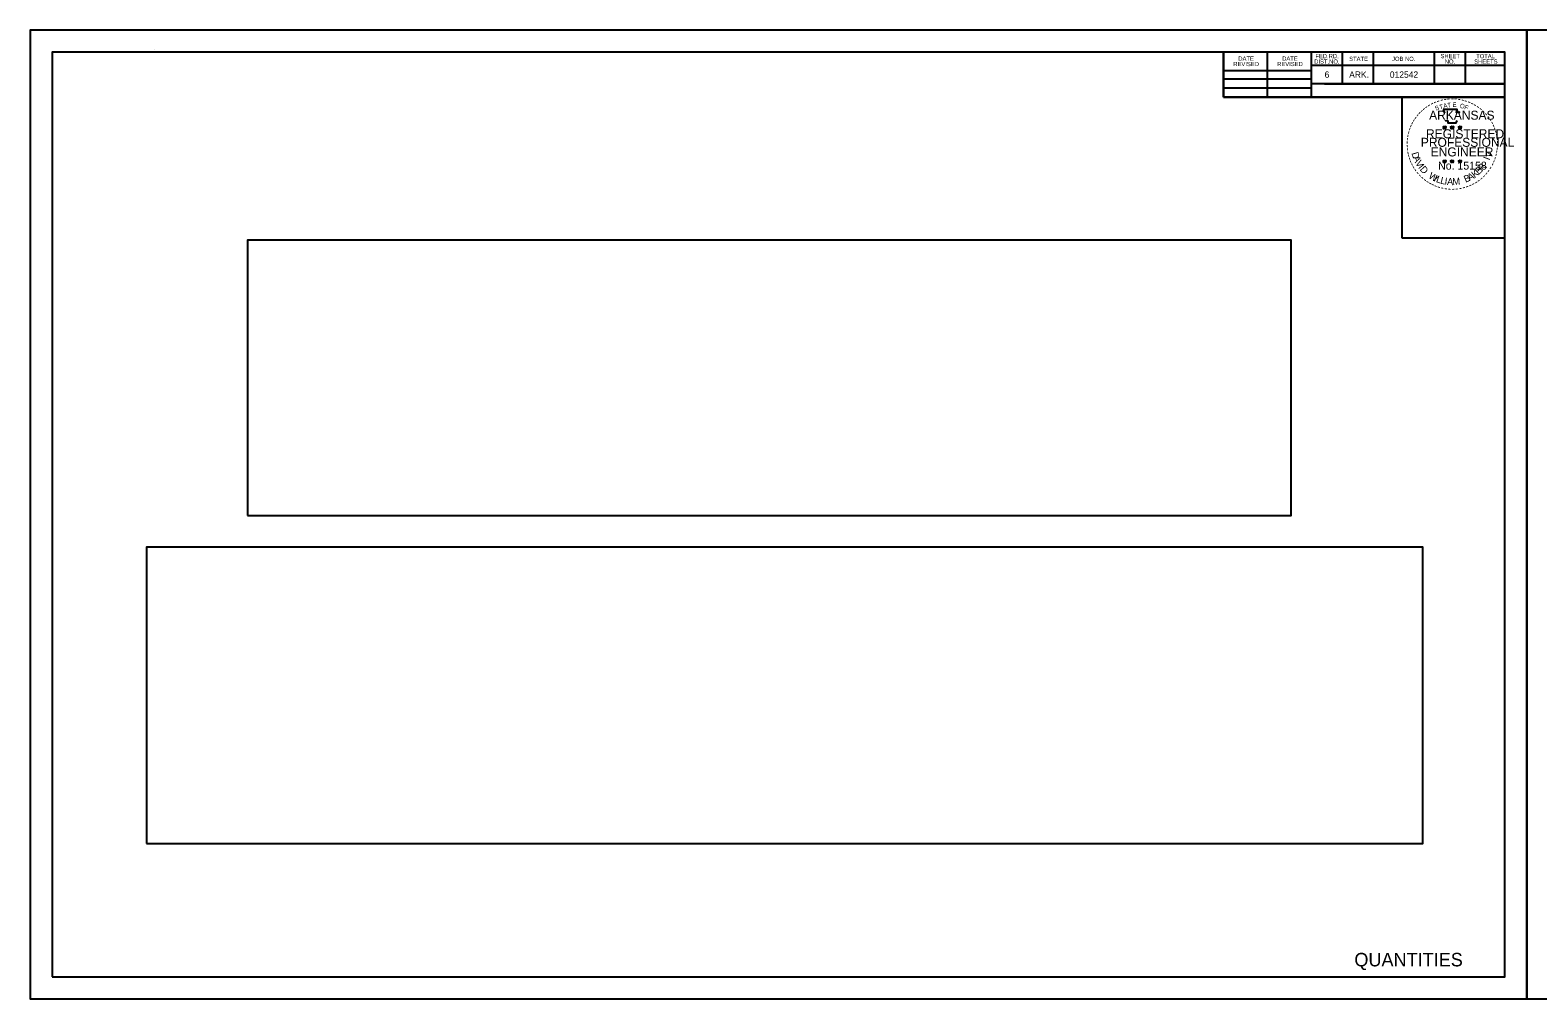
# Model space of a CAD drawing. Extents: x 2260866 to 2265966, y -3124874 to -3123774.
# Drawn here: x 2260866 to 2262578, y -3124874 to -3123774 of the extents above; entities that cross this region are included whole.
import ezdxf

# ---------------------------------------------------------------- set-up
doc = ezdxf.new("R2010")
doc.units = 0
for name, color, linetype in [('Default', 7, 'Continuous'), ('R_Border PE', 7, 'Continuous'), ('SHET_Annotations', 7, 'Continuous'), ('SHET_Border-Lines', 7, 'Continuous'), ('SHET_Border-Text', 7, 'Continuous'), ('SHET_Stamp-PE-Chief-Eng', 7, 'Continuous'), ('SHET_Stamp-Prelim', 7, 'Continuous'), ('SHET_Stamp-Seal', 7, 'Continuous')]:
    doc.layers.add(name, color=color, linetype=linetype)

msp = doc.modelspace()

# ---------------------------------------------------------------- linework, layer by layer
at = {"layer": 'Default'}
for points in [[(2260865.7, -3123773.5), (2260865.7, -3124873.5), (2262565.7, -3124873.5), (2262565.7, -3123773.5)], [(2262565.7, -3123773.5), (2262565.7, -3124873.5), (2264265.7, -3124873.5), (2264265.7, -3123773.5)], [(2261112.5, -3124324.8), (2262298, -3124324.8), (2262298, -3124011.9), (2261112.5, -3124011.9)], [(2260997.8, -3124697.3), (2262447.6, -3124697.3), (2262447.6, -3124360.6), (2260997.8, -3124360.6)]]:
    msp.add_lwpolyline(points, close=True, dxfattribs=at)
at = {"layer": 'R_Border PE'}
for p, q in [((2262470.5, -3123883.3), (2262472.3, -3123883.8)), ((2262470.5, -3123883.3), (2262471.8, -3123883.5)), ((2262470.5, -3123883.3), (2262471.7, -3123883.9)), ((2262471.2, -3123885.4), (2262472.3, -3123883.8)), ((2262471.2, -3123885.4), (2262471.8, -3123884.1)), ((2262471.2, -3123885.4), (2262472.3, -3123884.3)), ((2262472.3, -3123882), (2262472.1, -3123883.3)), ((2262472.3, -3123883.8), (2262472.3, -3123882)), ((2262472.3, -3123882), (2262472.5, -3123883.3)), ((2262474, -3123883.3), (2262472.3, -3123883.8)), ((2262473.4, -3123885.4), (2262472.3, -3123883.8)), ((2262473.4, -3123885.4), (2262472.3, -3123884.3)), ((2262474, -3123883.3), (2262472.6, -3123883.5)), ((2262473.4, -3123885.4), (2262472.7, -3123883.9)), ((2262474, -3123883.3), (2262473, -3123883.8)), ((2262479, -3123883.3), (2262480.8, -3123883.8)), ((2262479, -3123883.3), (2262480.3, -3123883.5)), ((2262479, -3123883.3), (2262480.2, -3123883.9)), ((2262479.7, -3123885.4), (2262480.8, -3123883.8)), ((2262479.7, -3123885.4), (2262480.3, -3123884.1)), ((2262479.7, -3123885.4), (2262480.8, -3123884.3)), ((2262480.8, -3123882), (2262480.6, -3123883.3)), ((2262480.8, -3123883.8), (2262480.8, -3123882)), ((2262480.8, -3123882), (2262481, -3123883.3)), ((2262482.6, -3123883.3), (2262480.8, -3123883.8)), ((2262481.9, -3123885.4), (2262480.8, -3123883.8)), ((2262481.9, -3123885.4), (2262480.8, -3123884.3)), ((2262482.6, -3123883.3), (2262481.1, -3123883.5)), ((2262481.9, -3123885.4), (2262481.2, -3123883.9)), ((2262482.6, -3123883.3), (2262481.5, -3123883.8)), ((2262488, -3123883.3), (2262489.8, -3123883.9)), ((2262488, -3123883.3), (2262489.3, -3123883.6)), ((2262488, -3123883.3), (2262489.2, -3123884)), ((2262488.7, -3123885.4), (2262489.8, -3123883.9)), ((2262488.7, -3123885.4), (2262489.3, -3123884.2)), ((2262488.7, -3123885.4), (2262489.8, -3123884.3)), ((2262489.8, -3123882), (2262489.6, -3123883.3)), ((2262489.8, -3123883.9), (2262489.8, -3123882)), ((2262489.8, -3123882), (2262490, -3123883.3)), ((2262491.6, -3123883.3), (2262489.8, -3123883.9)), ((2262490.9, -3123885.4), (2262489.8, -3123883.9)), ((2262490.9, -3123885.4), (2262489.8, -3123884.3)), ((2262491.6, -3123883.3), (2262490.1, -3123883.6)), ((2262490.9, -3123885.4), (2262490.2, -3123883.9)), ((2262491.6, -3123883.3), (2262490.5, -3123883.9)), ((2262470.5, -3123921.9), (2262472.3, -3123922.5)), ((2262470.5, -3123921.9), (2262471.8, -3123922.1)), ((2262470.5, -3123921.9), (2262471.7, -3123922.5)), ((2262471.2, -3123924), (2262472.3, -3123922.5)), ((2262471.2, -3123924), (2262471.8, -3123922.7)), ((2262471.2, -3123924), (2262472.2, -3123922.9)), ((2262472.3, -3123920.6), (2262472, -3123921.9)), ((2262473.3, -3123924), (2262472.2, -3123922.9)), ((2262472.3, -3123922.5), (2262472.3, -3123920.6)), ((2262472.3, -3123920.6), (2262472.5, -3123921.9)), ((2262474, -3123921.9), (2262472.3, -3123922.5)), ((2262473.3, -3123924), (2262472.3, -3123922.5)), ((2262474, -3123921.9), (2262472.6, -3123922.2)), ((2262473.3, -3123924), (2262472.6, -3123922.5)), ((2262474, -3123921.9), (2262473, -3123922.4)), ((2262479, -3123921.9), (2262480.8, -3123922.5)), ((2262479, -3123921.9), (2262480.3, -3123922.1)), ((2262479, -3123921.9), (2262480.2, -3123922.5)), ((2262479.7, -3123924), (2262480.8, -3123922.5)), ((2262479.7, -3123924), (2262480.3, -3123922.7)), ((2262479.7, -3123924), (2262480.8, -3123922.9)), ((2262480.8, -3123920.6), (2262480.6, -3123921.9)), ((2262480.8, -3123922.5), (2262480.8, -3123920.6)), ((2262480.8, -3123920.6), (2262481, -3123921.9)), ((2262482.5, -3123921.9), (2262480.8, -3123922.5)), ((2262481.9, -3123924), (2262480.8, -3123922.5)), ((2262481.9, -3123924), (2262480.8, -3123922.9)), ((2262482.5, -3123921.9), (2262481.1, -3123922.2)), ((2262481.9, -3123924), (2262481.2, -3123922.5)), ((2262482.5, -3123921.9), (2262481.5, -3123922.4)), ((2262488, -3123922), (2262489.8, -3123922.5)), ((2262488, -3123922), (2262489.3, -3123922.2)), ((2262488, -3123922), (2262489.2, -3123922.6)), ((2262488.7, -3123924), (2262489.8, -3123922.5)), ((2262488.7, -3123924), (2262489.3, -3123922.8)), ((2262488.7, -3123924), (2262489.8, -3123922.9)), ((2262489.8, -3123920.7), (2262489.6, -3123921.9)), ((2262489.8, -3123922.5), (2262489.8, -3123920.7)), ((2262489.8, -3123920.7), (2262490, -3123921.9)), ((2262491.5, -3123922), (2262489.8, -3123922.5)), ((2262490.9, -3123924), (2262489.8, -3123922.5)), ((2262490.9, -3123924), (2262489.8, -3123922.9)), ((2262491.5, -3123922), (2262490.1, -3123922.2)), ((2262490.9, -3123924), (2262490.2, -3123922.5)), ((2262491.5, -3123922), (2262490.5, -3123922.5))]:
    msp.add_line(p, q, dxfattribs=at)
for points in [[(2262470.7, -3123863.5), (2262472.1, -3123867.7)], [(2262488.6, -3123868.2), (2262489.3, -3123866.8), (2262485.8, -3123866.9), (2262486.6, -3123863.5), (2262470.7, -3123863.5)], [(2262473.2, -3123875.9), (2262473.2, -3123876.3), (2262476.1, -3123876.4), (2262475.8, -3123878.8), (2262485.3, -3123878.8), (2262486.4, -3123876.1)], [(2262480.8, -3123882), (2262481.9, -3123885.4), (2262479, -3123883.3), (2262482.6, -3123883.3), (2262479.7, -3123885.4), (2262480.8, -3123882)], [(2262489.8, -3123882), (2262490.9, -3123885.4), (2262488, -3123883.3), (2262491.6, -3123883.3), (2262488.7, -3123885.4), (2262489.8, -3123882)], [(2262472.3, -3123920.6), (2262473.3, -3123924), (2262470.5, -3123921.9), (2262474, -3123921.9), (2262471.2, -3123924), (2262472.3, -3123920.6)], [(2262480.8, -3123920.6), (2262481.9, -3123924), (2262479, -3123921.9), (2262482.5, -3123921.9), (2262479.7, -3123924), (2262480.8, -3123920.6)], [(2262489.8, -3123920.7), (2262490.9, -3123924), (2262488, -3123922), (2262491.5, -3123922), (2262488.7, -3123924), (2262489.8, -3123920.7)]]:
    msp.add_lwpolyline(points, dxfattribs=at)
for centre, radius in [((2262472.3, -3123883.9), 0.878), ((2262472.3, -3123883.9), 0.737), ((2262472.3, -3123883.9), 0.59), ((2262472.3, -3123883.9), 0.505), ((2262472.3, -3123883.9), 0.381), ((2262472.3, -3123883.9), 0.253), ((2262472.3, -3123883.9), 0.151), ((2262480.8, -3123883.9), 0.878), ((2262480.8, -3123883.9), 0.737), ((2262480.8, -3123883.9), 0.59), ((2262480.8, -3123883.9), 0.505), ((2262480.8, -3123883.9), 0.381), ((2262480.8, -3123883.9), 0.253), ((2262480.8, -3123883.9), 0.151), ((2262489.8, -3123883.9), 0.878), ((2262489.8, -3123883.9), 0.737), ((2262489.8, -3123883.9), 0.59), ((2262489.8, -3123883.9), 0.505), ((2262489.8, -3123883.9), 0.381), ((2262489.8, -3123883.9), 0.253), ((2262489.8, -3123883.9), 0.151), ((2262472.2, -3123922.5), 0.878), ((2262472.2, -3123922.5), 0.737), ((2262472.2, -3123922.5), 0.59), ((2262472.2, -3123922.5), 0.505), ((2262472.2, -3123922.5), 0.381), ((2262472.2, -3123922.5), 0.253), ((2262472.2, -3123922.5), 0.151), ((2262480.8, -3123922.5), 0.878), ((2262480.8, -3123922.5), 0.737), ((2262480.8, -3123922.5), 0.59), ((2262480.8, -3123922.5), 0.505), ((2262480.8, -3123922.5), 0.381), ((2262480.8, -3123922.5), 0.253), ((2262480.8, -3123922.5), 0.151), ((2262489.8, -3123922.5), 0.878), ((2262489.8, -3123922.5), 0.737), ((2262489.8, -3123922.5), 0.59), ((2262489.8, -3123922.5), 0.505), ((2262489.8, -3123922.5), 0.381), ((2262489.8, -3123922.5), 0.253), ((2262489.8, -3123922.5), 0.151)]:
    msp.add_circle(centre, radius, dxfattribs=at)
at = {"layer": 'SHET_Border-Lines'}
for p, q in [((2261006.8, -3123795), (2261006.8, -3123795)), ((2261006.8, -3123795), (2261006.8, -3123795)), ((2262221.2, -3123849.5), (2262221.2, -3123798.5)), ((2262271.1, -3123849.5), (2262271.1, -3123798.5)), ((2262320.9, -3123798.5), (2262320.9, -3123849.5)), ((2262355.8, -3123798.5), (2262355.8, -3123834.3)), ((2262391.2, -3123798.5), (2262391.2, -3123834.3)), ((2262460.4, -3123798.5), (2262460.4, -3123834.3)), ((2262495.8, -3123798.5), (2262495.8, -3123834.3)), ((2262221.2, -3123819.3), (2262320.9, -3123819.3)), ((2262540.7, -3123813.7), (2262320.9, -3123813.7)), ((2262540.7, -3123813.6), (2262540.7, -3123813.6)), ((2262221.2, -3123828.9), (2262320.9, -3123828.9)), ((2262221.2, -3123838.9), (2262320.9, -3123838.9)), ((2262540.7, -3123834.3), (2262320.9, -3123834.3)), ((2262336, -3123834.3), (2262540.7, -3123834.3)), ((2262540.7, -3123849.5), (2262221.2, -3123849.5))]:
    msp.add_line(p, q, dxfattribs=at)
for points in [[(2260865.7, -3124873.5), (2262565.7, -3124873.5), (2262565.7, -3123773.5), (2260865.7, -3123773.5)], [(2262565.7, -3124873.5), (2264265.7, -3124873.5), (2264265.7, -3123773.5), (2262565.7, -3123773.5)], [(2260890.7, -3124848.5), (2262540.7, -3124848.5), (2262540.7, -3123798.5), (2260890.7, -3123798.5)], [(2262221.2, -3123849.5), (2262540.7, -3123849.5), (2262540.7, -3123798.5), (2262221.2, -3123798.5)]]:
    msp.add_lwpolyline(points, close=True, dxfattribs=at)
at = {"layer": 'SHET_Stamp-PE-Chief-Eng'}
msp.add_lwpolyline([(2262472.3, -3123882), (2262473.4, -3123885.4), (2262470.5, -3123883.3), (2262474, -3123883.3), (2262471.2, -3123885.4), (2262472.3, -3123882)], dxfattribs=at)
at = {"layer": 'SHET_Stamp-Prelim'}
msp.add_lwpolyline([(2262430.7, -3123849.5), (2262430.9, -3123849.5), (2262430.9, -3123849.5), (2262430.7, -3123849.5)], close=True, dxfattribs=at)
at = {"layer": 'SHET_Stamp-Seal'}
msp.add_lwpolyline([(2262423.7, -3124009.2), (2262540.7, -3124009.2), (2262540.7, -3123849.5), (2262423.7, -3123849.5)], close=True, dxfattribs=at)

# ---------------------------------------------------------------- texts
at = {"layer": 'Default'}
msp.add_text('QUANTITIES', height=15.35, dxfattribs=at).set_placement((2262369.8, -3124836.7))
at = {"layer": 'R_Border PE'}
for s, height, rotation, p in [('-', 8.16, 28.7918, (2262457.9, -3123860.7)), ('-', 8.16, 24.3072, (2262461.1, -3123859.1)), ('-', 8.16, 19.1761, (2262464.3, -3123857.8)), ('-', 8.16, 13.6302, (2262468.1, -3123856.5)), ('A', 5.1, 11.2132, (2262471.2, -3123862.2)), ('-', 8.16, 10.2193, (2262471.6, -3123855.7)), ('T', 5.1, 6.0228, (2262475.5, -3123861.3)), ('-', 8.16, 5.8968, (2262475.3, -3123855.1)), ('-', 8.16, 0.1862, (2262479.3, -3123854.8)), ('E', 5.1, 0.8323, (2262481.2, -3123860.8)), ('-', 8.16, 357.743, (2262482.9, -3123854.8)), ('-', 8.16, 352.1617, (2262486.7, -3123855.1)), ('-', 8.16, 347.2049, (2262490.4, -3123855.7)), ('-', 8.16, 342.3362, (2262493.6, -3123856.5)), ('-', 8.16, 337.8551, (2262497.4, -3123857.6)), ('-', 8.16, 334.1211, (2262500.6, -3123859)), ('-', 8.16, 54.2325, (2262440.8, -3123876.5)), ('-', 8.16, 50.6142, (2262442.9, -3123873.6)), ('-', 8.16, 48.4231, (2262444.9, -3123871.1)), ('-', 8.16, 42.9622, (2262447.2, -3123868.7)), ('-', 8.16, 38.9507, (2262449.4, -3123866.6)), ('-', 8.16, 36.2317, (2262451.9, -3123864.6)), ('-', 8.16, 34.0636, (2262454.8, -3123862.6)), ('S', 5.1, 21.594, (2262462.3, -3123865.1)), ('T', 5.1, 16.4036, (2262467, -3123863.5)), ('O', 5.1, 350.4515, (2262489.3, -3123861.8)), ('F', 5.1, 340.0707, (2262494.2, -3123863)), ('-', 8.16, 329.6409, (2262503.6, -3123860.5)), ('-', 8.16, 325.8627, (2262506.8, -3123862.3)), ('-', 8.16, 320.5297, (2262510, -3123864.5)), ('-', 8.16, 315.5786, (2262513, -3123867)), ('-', 8.16, 309.8797, (2262515.9, -3123869.8)), ('-', 8.16, 306.6522, (2262518.6, -3123872.8)), ('-', 8.16, 75.461, (2262434.1, -3123892.3)), ('-', 8.16, 72.3945, (2262435.1, -3123888.7)), ('-', 8.16, 67.7743, (2262436.2, -3123885.4)), ('-', 8.16, 62.8713, (2262437.5, -3123882.3)), ('-', 8.16, 58.0706, (2262439.1, -3123879.2)), ('-', 7.14, 303.6753, (2262521.1, -3123875.7)), ('-', 8.16, 299.6684, (2262522.7, -3123878.8)), ('-', 8.16, 294.6628, (2262524.3, -3123881.9)), ('-', 8.16, 290.5728, (2262525.7, -3123884.9)), ('-', 8.16, 285.1233, (2262526.8, -3123887.8)), ('-', 8.16, 94.1959, (2262433.1, -3123906.7)), ('-', 8.16, 89.0622, (2262432.9, -3123903)), ('-', 8.16, 98.9479, (2262433.4, -3123910.1)), ('-', 8.16, 85.1863, (2262433, -3123899.5)), ('-', 8.16, 81.2013, (2262433.4, -3123895.9)), ('-', 8.16, 280.5493, (2262527.9, -3123891.6)), ('-', 8.16, 276.5962, (2262528.7, -3123895.6)), ('-', 8.16, 263.5172, (2262529.1, -3123905.9)), ('-', 8.16, 274.3301, (2262529, -3123899.2)), ('-', 8.16, 269.9407, (2262529.2, -3123902.5)), ('-', 8.16, 101.7149, (2262434.1, -3123913.9)), ('-', 8.16, 105.4578, (2262435, -3123916.9)), ('-', 8.16, 109.0874, (2262436.1, -3123920.1)), ('-', 8.16, 114.0643, (2262437.3, -3123923.2)), ('-', 8.16, 115.7289, (2262438.9, -3123926.3)), ('D', 7.85, 286.2848, (2262434.6, -3123913.2)), ('A', 7.85, 292.7835, (2262436.1, -3123918.3)), ('V', 7.85, 300.7936, (2262438.7, -3123924.3)), ('R', 7.85, 50.3651, (2262514.8, -3123934.5)), ('I', 7.85, 69.0301, (2262523.2, -3123921.8)), ('V', 7.85, 72.6573, (2262524.3, -3123919.1)), ('-', 8.16, 244.6197, (2262524.8, -3123923)), ('-', 8.16, 247.8887, (2262526.1, -3123919.7)), ('-', 8.16, 252.8681, (2262527.2, -3123916.3)), ('-', 8.16, 255.7626, (2262528.2, -3123912.6)), ('-', 8.16, 260.9953, (2262528.7, -3123909.2)), ('-', 8.16, 120.4471, (2262440.7, -3123929.3)), ('-', 8.16, 125.8934, (2262442.8, -3123932.2)), ('-', 8.16, 130.7181, (2262445.1, -3123935)), ('I', 7.85, 308.3502, (2262441.9, -3123929.6)), ('-', 8.16, 134.2238, (2262447.8, -3123937.8)), ('D', 7.85, 311.9774, (2262443.7, -3123932)), ('-', 8.16, 138.9338, (2262450.5, -3123940.1)), ('W', 7.85, 328.0731, (2262453.3, -3123941)), ('I', 7.85, 336.6877, (2262459.3, -3123944.6)), ('L', 7.85, 340.3149, (2262462, -3123945.8)), ('L', 7.85, 346.6625, (2262466.9, -3123947.6)), ('I', 7.85, 353.0101, (2262472, -3123948.8)), ('A', 7.85, 356.6373, (2262474.9, -3123949.2)), ('M', 7.85, 4.6473, (2262481.5, -3123949.5)), ('B', 7.85, 22.8589, (2262496.1, -3123946.8)), ('A', 7.85, 28.9042, (2262500.7, -3123944.9)), ('K', 7.85, 36.9143, (2262506.4, -3123941.7)), ('E', 7.85, 44.0175, (2262511, -3123938.1)), ('-', 8.16, 221.0851, (2262513.4, -3123938.5)), ('-', 8.16, 225.7653, (2262516.1, -3123935.9)), (',', 7.85, 57.4684, (2262518.4, -3123930)), ('-', 8.16, 231.2538, (2262518.5, -3123933)), ('-', 8.16, 233.8452, (2262520.7, -3123930.1)), ('-', 8.16, 239.0712, (2262522.7, -3123926.8)), ('-', 8.16, 144.6463, (2262453.3, -3123942.2)), ('-', 8.16, 148.0898, (2262456.1, -3123944.1)), ('-', 8.16, 151.5704, (2262459.1, -3123945.7)), ('-', 8.16, 154.6002, (2262461.8, -3123947)), ('-', 8.16, 158.5612, (2262464.9, -3123948.3)), ('-', 8.16, 162.7983, (2262468.4, -3123949.4)), ('-', 8.16, 167.5555, (2262472.1, -3123950.2)), ('-', 8.16, 173.1155, (2262476, -3123950.8)), ('-', 8.16, 176.5183, (2262479.8, -3123951.1)), ('-', 8.16, 181.5918, (2262483.6, -3123951)), ('-', 8.16, 185.8167, (2262487.8, -3123950.6)), ('-', 8.16, 191.2858, (2262491.5, -3123949.9)), ('-', 8.16, 195.4743, (2262495.2, -3123948.9)), ('-', 8.16, 199.4643, (2262498.6, -3123947.7)), ('-', 8.16, 204.2516, (2262501.8, -3123946.3)), ('-', 8.16, 207.3568, (2262505, -3123944.6)), ('-', 8.16, 212.2491, (2262507.9, -3123942.9)), ('-', 8.16, 215.7363, (2262510.6, -3123940.9))]:
    msp.add_text(s, height=height, rotation=rotation, dxfattribs=at).set_placement(p)
for s, height, p in [('ARKANSAS', 10.2, (2262454.7, -3123875.2)), ('REGISTERED', 10.2, (2262451.2, -3123896.3)), ('PROFESSIONAL', 10.2, (2262445.3, -3123906)), ('ENGINEER', 10.2, (2262456.5, -3123916.9)), ('No. 15158', 8.96, (2262464.9, -3123931.9)), ('AAMU', 0.000102, (2262480.4, -3123949.5))]:
    msp.add_text(s, height=height, dxfattribs=at).set_placement(p)
at = {"layer": 'SHET_Annotations'}
for s, p in [('6', (2262336, -3123827.6)), ('ARK.', (2262363.9, -3123827.6)), ('012542', (2262410.1, -3123827.6))]:
    msp.add_text(s, height=7.2, dxfattribs=at).set_placement(p)
at = {"layer": 'SHET_Border-Text'}
for s, p in [('DATE', (2262238, -3123808.2)), ('DATE', (2262287.8, -3123808.2)), ('FED.RD.', (2262325.5, -3123805.4)), ('STATE', (2262363.9, -3123808.5)), ('JOB NO.', (2262412.6, -3123808.5)), ('SHEET', (2262467.6, -3123805.4)), ('TOTAL', (2262508.1, -3123805.4)), ('REVISED', (2262232.3, -3123814.4)), ('REVISED', (2262282.1, -3123814.4)), ('DIST.NO.', (2262324.2, -3123811.6)), ('NO.', (2262472.5, -3123811.6)), ('SHEETS', (2262505.9, -3123811.6))]:
    msp.add_text(s, height=4.8, dxfattribs=at).set_placement(p)
at = {"layer": 'SHET_Stamp-Prelim'}
for s, height in [('PRELIMINARY', 0.013), ('SUBJECT TO REVISION', 0.009)]:
    msp.add_text(s, height=height, dxfattribs=at).set_placement((2262430.7, -3123849.5))

doc.saveas('drawing.dxf')
